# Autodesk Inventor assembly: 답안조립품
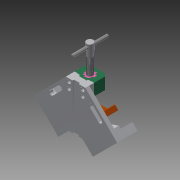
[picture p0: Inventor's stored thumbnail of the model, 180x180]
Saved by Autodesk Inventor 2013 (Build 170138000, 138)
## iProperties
Created: 2019-04
Part Number: 답안조립품
Document SubType Name: Assembly
Designer: Administrator
Author: Administrator
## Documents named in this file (11)
- C:\Users\Administrator\Desktop\490407V1004\답안조립품.iam
- C:\Users\Administrator\Desktop\490407V1004\본체.ipt
- C:\Users\Administrator\Desktop\490407V1004\리드스크류.ipt
- C:\Users\Administrator\Desktop\490407V1004\서포트.ipt
- C:\Users\Administrator\Desktop\490407V1004\조.ipt
- C:\Users\Administrator\Desktop\490407V1004\핸들.ipt
- C:\Users\Administrator\Desktop\490407V1004\평행 핀 2.5x24.ipt
- C:\Users\Administrator\Desktop\490407V1004\부시.ipt
- C:\Users\Administrator\Desktop\490407V1004\멈춤나사 M4x5.ipt
- C:\Users\Administrator\Desktop\490407V1004\멈춤나사 M4x10.ipt
- C:\Users\Administrator\Desktop\490407V1004\볼트 M4x16.ipt
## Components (1 placed, 1 different names)
1. 핸들:1
